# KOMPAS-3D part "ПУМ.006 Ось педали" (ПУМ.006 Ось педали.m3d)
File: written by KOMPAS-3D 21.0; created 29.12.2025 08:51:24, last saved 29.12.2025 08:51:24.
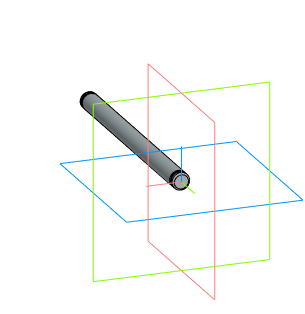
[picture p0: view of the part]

Document properties: Автор: Марсель; Организация: Марсель; Полное имя файла: C:\Users\User\Desktop\ПУ\ПУМ\ПУМ.006 Ось педали.m3d

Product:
- Part/product: ПУМ.006 Ось педали
    Комментарий: Марсель

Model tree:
1. Операция без истории:1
